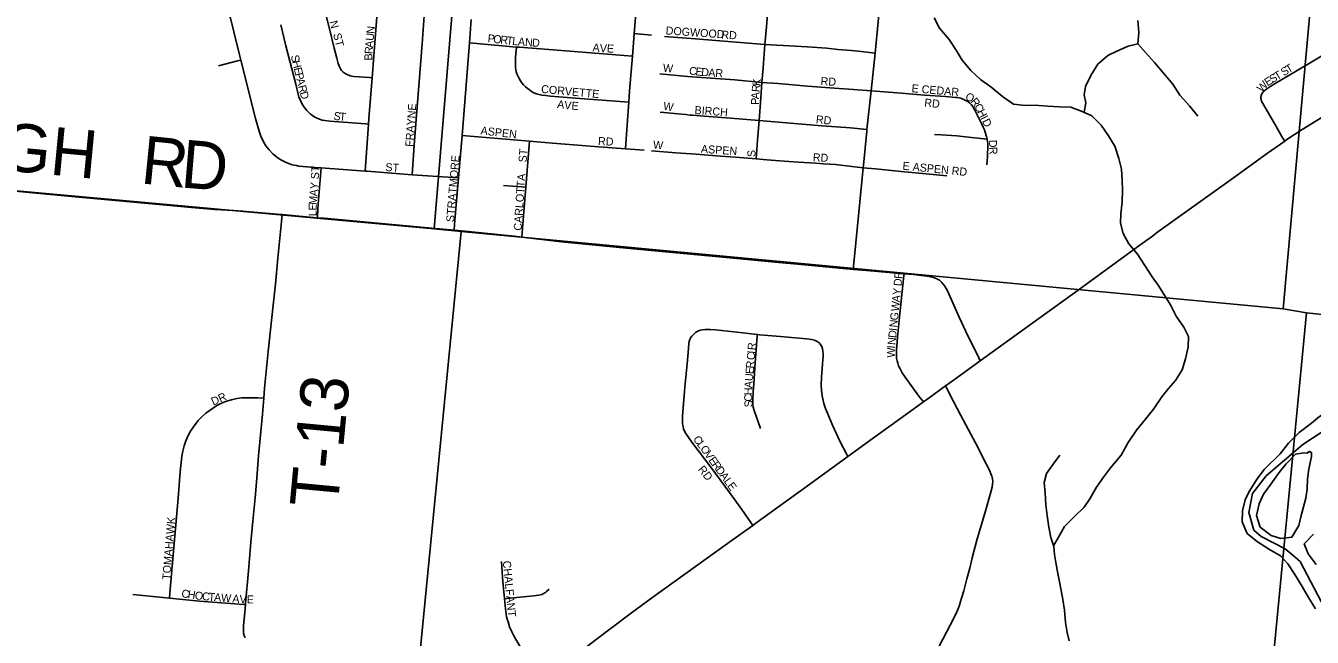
# Model space of a CAD drawing. Extents: x 0 to 680, y 0 to 440.
# Drawn here: x 150.24 to 174.06, y 261.68 to 273.01 of the extents above; entities that cross this region are included whole.
import ezdxf

# ---------------------------------------------------------------- set-up
doc = ezdxf.new("R2010")
doc.units = 0
for name, color, linetype in [('GM_X_County_Road', 7, 'Continuous'), ('GM_X_Major_River', 7, 'Continuous'), ('GM_X_Minor_River', 7, 'Continuous'), ('GM_X_Section', 7, 'Continuous'), ('GM_X_Township', 7, 'Continuous'), ('GM_X_Township_Road', 7, 'Continuous'), ('GM_X_Township_Road_Text', 7, 'Continuous'), ('GM_X_Township_Subdivision', 7, 'Continuous'), ('GM_X_Township_Subdivision_Text', 7, 'Continuous')]:
    doc.layers.add(name, color=color, linetype=linetype)

msp = doc.modelspace()

# ---------------------------------------------------------------- linework, layer by layer
at = {"layer": 'GM_X_County_Road'}
for points in [[(173.552, 270.873), (173.591, 270.9), (173.876, 271.086), (174.577, 271.522), (175.114, 271.853), (175.734, 272.237), (176.024, 272.413), (176.171, 272.503)], [(170.958, 269.009), (171.101, 269.114), (171.178, 269.173), (172.602, 270.194), (173.233, 270.648), (173.552, 270.873)], [(167.915, 266.802), (168.466, 267.203), (169.726, 268.114), (170.827, 268.913), (170.958, 269.009)], [(167.272, 266.337), (167.482, 266.489), (167.915, 266.802)], [(166.86, 266.04), (166.97, 266.119), (167.272, 266.337)], [(165.461, 265.029), (165.911, 265.355), (166.418, 265.724), (166.86, 266.04)], [(163.702, 263.755), (163.784, 263.815), (164.69, 264.471), (165.461, 265.029)], [(160.387, 261.323), (160.647, 261.525), (161.031, 261.816), (161.458, 262.137), (161.851, 262.423), (163.232, 263.417), (163.702, 263.755)]]:
    msp.add_lwpolyline(points, dxfattribs=at)
at = {"layer": 'GM_X_Major_River'}
for points in [[(176.639, 264.891), (176.325, 265.293), (176.105, 265.49), (175.902, 265.679), (175.709, 265.797), (175.55, 265.855), (175.337, 265.914), (175.178, 265.954), (174.983, 265.995), (174.774, 265.995), (174.565, 265.953), (174.349, 265.864), (174.198, 265.773), (174.046, 265.646), (173.821, 265.473), (173.625, 265.277), (173.471, 265.078)], [(173.471, 265.078), (173.172, 264.788), (173.03, 264.601), (172.894, 264.385), (172.819, 264.226), (172.772, 264.025), (172.767, 263.823), (172.856, 263.607), (173.048, 263.447), (173.27, 263.305), (173.475, 263.193), (173.608, 263.041), (173.74, 262.847), (173.877, 262.624), (173.99, 262.419), (174.122, 262.207)], [(173.75, 265.076), (173.579, 264.896), (173.45, 264.733), (173.295, 264.517), (173.16, 264.33), (173.078, 264.154), (173.031, 263.935), (173.097, 263.72), (173.301, 263.566), (173.478, 263.514), (173.686, 263.538), (173.811, 263.755), (173.851, 263.915), (173.903, 264.098), (173.943, 264.257), (173.965, 264.423), (173.976, 264.619), (173.998, 264.797), (174.047, 265.033)], [(174.047, 265.033), (174.049, 265.099), (174.025, 265.117), (174.008, 265.124), (173.965, 265.095), (173.906, 265.1), (173.75, 265.076)], [(174.086, 263.594), (173.915, 263.414), (173.987, 263.227), (174.137, 263.027)]]:
    msp.add_lwpolyline(points, dxfattribs=at)
at = {"layer": 'GM_X_Minor_River'}
for points in [[(170.524, 265.056), (170.651, 265.292), (170.809, 265.516), (170.971, 265.722), (171.122, 265.91), (171.279, 266.134), (171.4, 266.287), (171.532, 266.439), (171.653, 266.634), (171.715, 266.841), (171.766, 267.054), (171.768, 267.256), (171.687, 267.424), (171.541, 267.628), (171.437, 267.837), (171.344, 267.987), (171.21, 268.202), (171.099, 268.358), (170.959, 268.568), (170.825, 268.777), (170.668, 268.969), (170.563, 269.161), (170.512, 269.352), (170.52, 269.524), (170.541, 269.749), (170.549, 269.963), (170.54, 270.147), (170.531, 270.355), (170.48, 270.552), (170.405, 270.779), (170.289, 270.97), (170.155, 271.168), (169.979, 271.343), (169.802, 271.422), (169.589, 271.502), (169.381, 271.505), (169.168, 271.519), (168.996, 271.533), (168.687, 271.537), (168.527, 271.557), (168.327, 271.696), (168.11, 271.877), (167.922, 272.004), (167.74, 272.179), (167.576, 272.371), (167.465, 272.557), (167.337, 272.754), (167.162, 272.964), (167.063, 273.156)], [(169.837, 271.407), (169.869, 271.582), (169.841, 271.731), (169.861, 271.885), (169.959, 272.086), (170.092, 272.298), (170.278, 272.456), (170.445, 272.537), (170.654, 272.629), (170.833, 272.675), (170.853, 272.882), (170.832, 273.108)], [(170.833, 272.675), (170.973, 272.512), (171.143, 272.326), (171.307, 272.128), (171.482, 271.924), (171.61, 271.726), (171.786, 271.528), (171.944, 271.336)], [(169.559, 261.616), (169.526, 261.771), (169.493, 261.955), (169.472, 262.187), (169.44, 262.384), (169.412, 262.55), (169.379, 262.711), (169.352, 262.866), (169.313, 263.069), (169.291, 263.217), (169.276, 263.366), (169.219, 263.527), (169.186, 263.724), (169.153, 263.938), (169.126, 264.135), (169.118, 264.354), (169.097, 264.551), (169.141, 264.717), (169.262, 264.887), (169.385, 265.057)], [(169.272, 263.376), (169.361, 263.537), (169.471, 263.732), (169.651, 263.913), (169.838, 264.089), (169.941, 264.248), (170.069, 264.46), (170.196, 264.648), (170.323, 264.819), (170.524, 265.056)]]:
    msp.add_lwpolyline(points, dxfattribs=at)
at = {"layer": 'GM_X_Section'}
for points in [[(143.224, 286.379), (143.238, 286.516), (159.118, 285.103), (157.8, 269.245), (141.851, 270.701)], [(159.118, 285.103), (174.94, 283.442), (173.525, 267.764), (158.298, 269.195), (157.8, 269.245)], [(174.94, 283.442), (190.555, 281.787), (188.936, 266.093), (173.956, 267.691), (173.525, 267.764)], [(158.298, 269.195), (173.525, 267.764), (173.956, 267.691), (172.459, 252.156), (156.776, 253.584)], [(173.956, 267.691), (188.936, 266.093), (190.144, 265.991), (188.668, 250.631), (172.459, 252.156)]]:
    msp.add_lwpolyline(points, close=True, dxfattribs=at)
at = {"layer": 'GM_X_Township'}
for points in [[(174.424, 261.966), (173.841, 263.085), (173.708, 263.195), (173.561, 263.318), (173.118, 263.551), (172.978, 263.668), (172.885, 263.994), (172.954, 264.344), (173.211, 264.671), (173.887, 265.254), (174.564, 265.697)], [(174.564, 265.697), (173.887, 265.254), (173.211, 264.671), (172.954, 264.344), (172.885, 263.994), (172.978, 263.668), (173.118, 263.551), (173.561, 263.318), (173.708, 263.195), (173.841, 263.085), (174.424, 261.966)]]:
    msp.add_lwpolyline(points, dxfattribs=at)
at = {"layer": 'GM_X_Township_Road'}
for points in [[(165.965, 272.502), (166.035, 273.213)], [(165.891, 271.804), (165.965, 272.502)], [(165.815, 271.086), (165.891, 271.804)], [(165.746, 270.38), (165.751, 270.427), (165.812, 271.056), (165.815, 271.086)], [(143.887, 270.537), (144.178, 270.516), (144.988, 270.436), (146.804, 270.262), (147.532, 270.19), (148.112, 270.132), (148.841, 270.062), (149.664, 269.985), (150.298, 269.921), (151.221, 269.835), (151.9, 269.771), (152.774, 269.692), (153.309, 269.643), (153.74, 269.605), (154.084, 269.584)], [(165.564, 268.495), (165.569, 268.553), (165.587, 268.734), (165.746, 270.38)], [(154.084, 269.584), (154.256, 269.573)], [(154.256, 269.573), (154.32, 269.569), (154.894, 269.519), (154.987, 269.511)], [(154.645, 266.109), (154.661, 266.299), (154.727, 266.973), (154.786, 267.55), (154.822, 267.887), (154.859, 268.225), (154.908, 268.707), (154.974, 269.384), (154.987, 269.511)], [(154.987, 269.511), (155.233, 269.489), (155.635, 269.453)], [(155.635, 269.453), (155.764, 269.442), (156.827, 269.346), (157.551, 269.28), (158.17, 269.221)], [(158.17, 269.221), (158.372, 269.202), (159.096, 269.132), (159.289, 269.112), (159.426, 269.096)], [(159.426, 269.096), (160.157, 269.008), (161.362, 268.89), (163.343, 268.703), (164.118, 268.631), (164.598, 268.586), (165.179, 268.53), (165.564, 268.495)], [(165.564, 268.495), (165.806, 268.473), (166.502, 268.415)], [(166.502, 268.415), (166.679, 268.4), (166.873, 268.379), (166.969, 268.364), (167.018, 268.353), (167.066, 268.339), (167.112, 268.321), (167.156, 268.295), (167.195, 268.262), (167.228, 268.225), (167.257, 268.184), (167.306, 268.098), (167.526, 267.611), (167.649, 267.348), (167.839, 266.955), (167.86, 266.911), (167.915, 266.802)], [(167.085, 261.385), (167.359, 261.905), (167.467, 262.124), (167.524, 262.259), (167.55, 262.345), (167.564, 262.407), (167.607, 262.541), (167.667, 262.762), (167.72, 262.961), (167.761, 263.154), (167.851, 263.483), (168.015, 264.043), (168.097, 264.324), (168.134, 264.465), (168.143, 264.515), (168.145, 264.566), (168.14, 264.616), (168.128, 264.665), (168.112, 264.712), (168.093, 264.758), (168.072, 264.802), (167.98, 264.974), (167.872, 265.191), (167.552, 265.791), (167.419, 266.051), (167.289, 266.304), (167.272, 266.337)], [(154.304, 262.285), (154.305, 262.292), (154.307, 262.309), (154.361, 262.914), (154.373, 263.059), (154.407, 263.445), (154.442, 263.832), (154.486, 264.266), (154.51, 264.556), (154.55, 265.041), (154.619, 265.815), (154.645, 266.109)], [(154.307, 261.673), (154.297, 261.687), (154.283, 261.714), (154.272, 261.758), (154.268, 261.804), (154.27, 261.898), (154.293, 262.14), (154.304, 262.285)]]:
    msp.add_lwpolyline(points, dxfattribs=at)
at = {"layer": 'GM_X_Township_Subdivision'}
for points in [[(154.221, 272.373), (154.198, 272.468), (153.999, 273.271), (153.93, 273.554), (153.795, 274.071), (153.761, 274.207)], [(156.65, 272.046), (156.68, 272.45), (156.737, 273.174), (156.763, 273.534), (156.798, 274.019), (156.804, 274.097)], [(155.701, 273.591), (155.857, 272.975), (155.95, 272.595), (156, 272.406), (156.025, 272.311), (156.038, 272.266), (156.047, 272.246), (156.057, 272.226), (156.072, 272.201), (156.087, 272.18), (156.103, 272.162), (156.118, 272.148), (156.136, 272.134), (156.155, 272.122), (156.176, 272.11), (156.198, 272.099), (156.22, 272.091), (156.247, 272.082), (156.277, 272.076), (156.311, 272.07), (156.409, 272.061), (156.599, 272.049), (156.65, 272.046)], [(161.504, 272.864), (161.54, 273.302)], [(163.926, 272.664), (163.954, 272.99), (163.988, 273.381)], [(157.391, 270.25), (157.43, 270.796), (157.485, 271.506), (157.517, 271.895), (157.576, 272.671), (157.616, 273.191)], [(158.452, 272.691), (158.486, 273.127)], [(156.585, 271.186), (156.536, 271.19), (156.112, 271.221), (155.869, 271.239), (155.773, 271.252), (155.725, 271.263), (155.679, 271.277), (155.633, 271.295), (155.59, 271.317), (155.549, 271.344), (155.511, 271.374), (155.441, 271.442), (155.409, 271.479), (155.381, 271.518), (155.355, 271.559), (155.312, 271.647), (155.295, 271.692), (155.281, 271.739), (155.236, 271.928), (155.052, 272.634), (154.958, 273.025)], [(161.471, 272.446), (161.497, 272.771), (161.504, 272.864)], [(161.504, 272.864), (161.828, 272.835)], [(162.063, 272.812), (162.642, 272.767), (163.926, 272.664)], [(158.316, 270.979), (158.452, 272.691)], [(158.452, 272.691), (159.323, 272.614)], [(159.323, 272.614), (159.309, 272.42), (159.305, 272.35), (159.305, 272.271), (159.308, 272.232), (159.313, 272.196), (159.321, 272.156), (159.334, 272.116), (159.367, 272.042), (159.398, 271.99), (159.427, 271.949), (159.456, 271.915), (159.491, 271.879), (159.523, 271.851), (159.565, 271.82), (159.605, 271.794), (159.649, 271.769), (159.698, 271.748), (159.744, 271.733), (159.797, 271.722), (159.865, 271.714), (159.954, 271.704), (160.42, 271.67), (161.405, 271.593)], [(159.323, 272.614), (159.38, 272.61), (160.855, 272.496), (161.471, 272.446)], [(163.867, 271.956), (163.891, 272.228), (163.926, 272.664)], [(163.926, 272.664), (164.484, 272.628), (164.709, 272.616), (165.07, 272.592), (165.276, 272.572), (165.528, 272.551), (165.71, 272.532), (165.965, 272.502)], [(173.552, 270.873), (173.507, 270.948), (173.385, 271.154), (173.164, 271.536), (173.146, 271.569), (173.13, 271.6), (173.124, 271.617), (173.118, 271.632), (173.115, 271.641), (173.113, 271.653), (173.112, 271.665), (173.111, 271.678), (173.112, 271.691), (173.114, 271.702), (173.116, 271.714), (173.119, 271.723), (173.126, 271.74), (173.131, 271.75), (173.14, 271.764), (173.146, 271.773), (173.154, 271.782), (173.167, 271.796), (173.176, 271.804), (173.19, 271.816), (173.22, 271.838), (173.258, 271.865), (173.295, 271.89), (173.375, 271.94), (174.021, 272.321), (174.659, 272.704)], [(153.806, 272.267), (154.158, 272.357), (154.221, 272.373)], [(155.705, 270.377), (155.588, 270.386), (155.296, 270.41), (155.248, 270.418), (155.199, 270.428), (155.151, 270.441), (155.059, 270.476), (154.971, 270.52), (154.928, 270.546), (154.888, 270.574), (154.812, 270.637), (154.743, 270.708), (154.682, 270.786), (154.631, 270.871), (154.589, 270.961), (154.557, 271.054), (154.494, 271.289), (154.221, 272.373)], [(161.405, 271.593), (161.419, 271.803), (161.471, 272.446)], [(161.978, 272.116), (162.495, 272.068), (162.753, 272.049), (163.368, 272.004), (163.867, 271.956)], [(156.585, 271.186), (156.593, 271.293), (156.65, 272.046)], [(163.82, 271.252), (163.848, 271.671), (163.867, 271.956)], [(163.867, 271.956), (164.169, 271.938), (164.714, 271.89), (165.13, 271.856), (165.565, 271.826), (165.891, 271.804)], [(165.891, 271.804), (166.216, 271.779), (166.455, 271.76), (166.88, 271.726), (167.273, 271.697), (167.459, 271.682), (167.493, 271.678), (167.521, 271.673), (167.552, 271.665), (167.577, 271.657), (167.598, 271.649), (167.642, 271.627)], [(168.042, 270.908), (168.03, 270.96), (168.004, 271.038), (167.99, 271.078), (167.969, 271.133), (167.935, 271.199), (167.812, 271.443), (167.78, 271.499), (167.749, 271.543), (167.713, 271.583), (167.69, 271.601), (167.663, 271.617), (167.642, 271.627)], [(161.342, 270.73), (161.375, 271.173), (161.405, 271.593)], [(161.987, 271.407), (162.321, 271.38), (162.46, 271.365), (162.544, 271.355), (162.586, 271.351), (162.807, 271.333), (163.287, 271.298), (163.82, 271.252)], [(156.522, 270.315), (156.585, 271.186)], [(163.763, 270.542), (163.789, 270.892), (163.82, 271.252)], [(163.82, 271.252), (163.962, 271.239), (164.977, 271.156), (165.509, 271.115), (165.815, 271.086)], [(158.25, 270.189), (158.316, 270.979)], [(158.316, 270.979), (159.566, 270.871)], [(167.064, 270.996), (167.19, 270.987), (167.384, 270.974), (167.477, 270.967), (167.698, 270.943), (168.042, 270.908)], [(168.034, 270.432), (168.045, 270.578), (168.05, 270.673), (168.053, 270.713), (168.053, 270.77), (168.052, 270.825), (168.048, 270.866), (168.042, 270.908)], [(159.5, 270.018), (159.566, 270.871)], [(159.566, 270.871), (159.991, 270.834), (160.769, 270.772), (161.342, 270.73)], [(161.342, 270.73), (161.687, 270.707)], [(161.827, 270.694), (162.273, 270.657), (162.655, 270.63), (163.101, 270.594), (163.384, 270.572), (163.763, 270.542)], [(163.763, 270.542), (163.961, 270.525), (164.281, 270.499), (164.548, 270.482), (164.867, 270.462), (165.012, 270.452), (165.13, 270.445), (165.23, 270.438), (165.534, 270.404), (165.746, 270.38)], [(155.635, 269.453), (155.637, 269.483), (155.654, 269.709), (155.705, 270.377)], [(156.522, 270.315), (155.705, 270.377)], [(157.391, 270.25), (157.236, 270.261), (156.558, 270.313), (156.522, 270.315)], [(158.25, 270.189), (158.155, 270.195), (157.391, 270.25)], [(165.746, 270.38), (165.974, 270.358), (166.513, 270.305), (166.913, 270.265), (167.295, 270.227)], [(158.17, 269.221), (158.179, 269.331), (158.25, 270.189)], [(159.084, 270.047), (159.5, 270.018)], [(159.426, 269.096), (159.433, 269.18), (159.5, 270.018)], [(166.86, 266.04), (166.779, 266.15), (166.522, 266.498), (166.468, 266.579), (166.422, 266.666), (166.402, 266.71), (166.386, 266.757), (166.373, 266.805), (166.365, 266.853), (166.361, 266.902), (166.363, 267), (166.383, 267.24), (166.426, 267.671), (166.499, 268.382), (166.502, 268.415)], [(163.702, 263.755), (163.664, 263.81), (163.496, 264.048), (163.27, 264.363), (162.923, 264.831), (162.691, 265.142), (162.573, 265.295), (162.514, 265.374), (162.46, 265.455), (162.436, 265.5), (162.42, 265.544), (162.41, 265.589), (162.4, 265.634), (162.397, 265.682), (162.399, 265.779), (162.445, 266.312), (162.485, 266.746), (162.509, 267.031), (162.518, 267.132), (162.522, 267.158), (162.528, 267.179), (162.548, 267.226), (162.572, 267.26), (162.602, 267.292), (162.641, 267.325), (162.686, 267.351), (162.726, 267.368), (162.771, 267.377), (162.819, 267.383), (162.868, 267.383), (162.914, 267.382), (163.009, 267.374), (163.352, 267.337), (163.788, 267.291)], [(163.847, 265.549), (163.729, 265.883), (163.711, 265.943), (163.703, 265.991), (163.7, 266.046), (163.702, 266.088), (163.709, 266.235), (163.719, 266.378), (163.747, 266.764), (163.785, 267.258), (163.788, 267.291)], [(163.788, 267.291), (163.826, 267.287), (164.212, 267.25), (164.694, 267.21), (164.791, 267.198), (164.841, 267.184), (164.884, 267.164), (164.922, 267.139), (164.953, 267.104), (164.977, 267.067), (164.99, 267.025), (165.001, 266.981), (165.006, 266.935), (165.006, 266.887), (164.994, 266.743), (164.974, 266.501), (164.97, 266.354), (164.972, 266.256), (164.983, 266.157), (165.018, 266.015), (165.048, 265.922), (165.083, 265.831), (165.179, 265.608), (165.321, 265.299), (165.435, 265.078), (165.461, 265.029)], [(152.898, 262.406), (152.906, 262.501), (153.057, 264.26), (153.097, 264.744), (153.128, 265.035), (153.146, 265.131), (153.171, 265.226), (153.203, 265.319), (153.241, 265.409), (153.287, 265.497), (153.341, 265.579), (153.432, 265.695), (153.499, 265.766), (153.573, 265.831), (153.651, 265.891), (153.774, 265.972), (153.86, 266.018), (153.952, 266.054), (154.047, 266.082), (154.143, 266.102), (154.24, 266.114), (154.338, 266.119), (154.485, 266.117), (154.534, 266.115), (154.645, 266.109)], [(159.102, 262.394), (159.101, 262.403), (159.076, 262.646), (159.066, 262.792), (159.046, 263.087)], [(159.102, 262.394), (159.146, 262.399), (159.641, 262.449), (159.741, 262.465), (159.792, 262.476), (159.818, 262.487), (159.839, 262.497), (159.852, 262.504), (159.865, 262.512), (159.883, 262.528), (159.929, 262.576)], [(152.219, 262.475), (152.346, 262.462), (152.898, 262.406)], [(152.898, 262.406), (153.453, 262.35), (154.188, 262.294), (154.283, 262.286), (154.304, 262.285)], [(159.855, 260.909), (159.795, 260.984), (159.643, 261.173), (159.495, 261.369), (159.383, 261.53), (159.306, 261.655), (159.267, 261.724), (159.237, 261.785), (159.198, 261.874), (159.168, 261.968), (159.152, 262.019), (159.142, 262.062), (159.132, 262.11), (159.12, 262.207), (159.102, 262.394)]]:
    msp.add_lwpolyline(points, dxfattribs=at)

# ---------------------------------------------------------------- texts
at = {"layer": 'GM_X_Township_Road_Text'}
for s, height, rotation, p in [('GERLAUGH', 0.8894, 354.5349, (144.875, 270.808)), ('R', 0.889, 354.2451, (152.348, 270.091)), ('D', 0.889, 355.2013, (153.09, 270.016)), ('T-13', 0.8894, 84.6178, (156.01, 264.054))]:
    msp.add_text(s, height=height, rotation=rotation, dxfattribs=at).set_placement(p)
at = {"layer": 'GM_X_Township_Subdivision_Text'}
for s, height, rotation, p in [('N', 0.148, 284.3013, (155.862, 273.085)), ('ST', 0.1482, 284.0363, (155.927, 272.854)), ('U', 0.148, 84.6809, (156.679, 272.725)), ('N', 0.148, 84.6934, (156.691, 272.855)), ('P', 0.148, 353.8137, (158.785, 272.705)), ('O', 0.148, 353.8135, (158.889, 272.694)), ('R', 0.148, 353.8177, (159.019, 272.68)), ('T', 0.148, 353.8001, (159.135, 272.667)), ('DOGWOOD', 0.1482, 356.0809, (162.084, 272.849)), ('RD', 0.1482, 356.989, (163.115, 272.771)), ('R', 0.148, 85.2958, (156.658, 272.479)), ('A', 0.148, 84.6918, (156.667, 272.595)), ('L', 0.148, 353.9055, (159.24, 272.656)), ('A', 0.148, 355.2745, (159.347, 272.645)), ('N', 0.148, 356.0294, (159.479, 272.634)), ('D', 0.148, 356.0519, (159.609, 272.625)), ('A', 0.148, 354.7472, (160.729, 272.536)), ('V', 0.148, 356.5757, (160.864, 272.523)), ('E', 0.148, 356.9863, (160.995, 272.516)), ('S', 0.148, 283.5823, (155.144, 272.449)), ('H', 0.148, 283.5837, (155.169, 272.347)), ('B', 0.148, 88.3485, (156.654, 272.363)), ('E', 0.148, 283.5823, (155.199, 272.22)), ('P', 0.148, 283.5823, (155.224, 272.119)), ('W', 0.148, 355.6039, (162.033, 272.157)), ('C', 0.148, 353.7094, (162.516, 272.105)), ('E', 0.148, 354.0135, (162.634, 272.092)), ('D', 0.148, 355.5448, (162.742, 272.081)), ('A', 0.148, 356.0348, (162.873, 272.071)), ('R', 0.148, 356.0518, (163.003, 272.062)), ('S', 0.148, 31.5869, (173.322, 271.94)), ('T', 0.148, 31.3784, (173.411, 271.995)), ('S', 0.148, 31.3784, (173.534, 272.07)), ('T', 0.148, 31.3667, (173.623, 272.124)), ('A', 0.148, 283.5803, (155.248, 272.018)), ('R', 0.148, 283.5872, (155.279, 271.891)), ('CORVETTE', 0.1482, 354.8053, (159.777, 271.766)), ('R', 0.148, 83.9052, (163.826, 271.773)), ('K', 0.148, 83.836, (163.839, 271.89)), ('RD', 0.1482, 356.9887, (164.954, 271.91)), ('E CEDAR', 0.1482, 355.1554, (166.637, 271.779)), ('W', 0.148, 46.5041, (173.126, 271.767)), ('E', 0.148, 32.6179, (173.235, 271.884)), ('D', 0.148, 286.3408, (155.309, 271.769)), ('A', 0.148, 353.1759, (160.073, 271.487)), ('P', 0.148, 89.3033, (163.816, 271.542)), ('A', 0.148, 85.7119, (163.817, 271.644)), ('RD', 0.1482, 353.9883, (166.872, 271.515)), ('O', 0.148, 331.7585, (167.621, 271.654)), ('R', 0.148, 308.5991, (167.724, 271.602)), ('S', 0.148, 352.2582, (155.93, 271.27)), ('T', 0.148, 354.421, (156.039, 271.256)), ('FRAYNE', 0.1482, 85.9147, (157.412, 270.762)), ('V', 0.148, 353.5312, (160.203, 271.471)), ('E', 0.148, 355.7277, (160.339, 271.456)), ('W', 0.148, 351.2507, (162.035, 271.453)), ('BIRCH', 0.1482, 355.914, (162.619, 271.375)), ('C', 0.148, 300.2057, (167.794, 271.515)), ('H', 0.148, 297.7723, (167.852, 271.415)), ('RD', 0.1482, 353.994, (164.864, 271.205)), ('I', 0.148, 297.3372, (167.913, 271.3)), ('D', 0.148, 296.179, (167.942, 271.242)), ('ASPEN', 0.1482, 353.5154, (158.655, 270.997)), ('RD', 0.1482, 356.9887, (160.832, 270.801)), ('ST', 0.1482, 86.4254, (159.511, 270.475)), ('W', 0.148, 355.6039, (161.85, 270.736)), ('ASPEN', 0.1482, 356.0991, (162.737, 270.657)), ('S', 0.148, 90, (163.75, 270.577)), ('D', 0.148, 273.2914, (168.072, 270.892)), ('R', 0.148, 272.6969, (168.079, 270.762)), ('ST', 0.1482, 356.4186, (156.893, 270.318)), ('STRATMORE', 0.1482, 85.2364, (158.168, 269.367)), ('RD', 0.1482, 356.9833, (164.81, 270.501)), ('E ASPEN RD', 0.1482, 354.3592, (166.469, 270.344)), ('ST', 0.1482, 86.4254, (155.663, 270.162)), ('CARLOTTA', 0.1482, 86.1853, (159.42, 269.21)), ('A', 0.148, 84.6374, (155.637, 269.843)), ('Y', 0.148, 84.6484, (155.649, 269.973)), ('M', 0.148, 85.7612, (155.625, 269.688)), ('E', 0.148, 89.2623, (155.624, 269.586)), ('L', 0.148, 89.8907, (155.624, 269.482)), ('D', 0.148, 84.1426, (166.454, 268.18)), ('R', 0.148, 86.141, (166.468, 268.316)), ('Y', 0.148, 84.1407, (166.437, 268.012)), ('W', 0.148, 84.1472, (166.406, 267.713)), ('A', 0.148, 84.1426, (166.423, 267.882)), ('G', 0.148, 84.1407, (166.389, 267.545)), ('D', 0.148, 84.1437, (166.355, 267.22)), ('I', 0.148, 84.1491, (166.369, 267.35)), ('N', 0.148, 84.1437, (166.375, 267.415)), ('R', 0.148, 85.0973, (163.75, 266.994)), ('N', 0.148, 84.2089, (166.342, 267.09)), ('C', 0.148, 85.1123, (163.735, 266.812)), ('I', 0.148, 85.0984, (163.745, 266.929)), ('W', 0.148, 88.7053, (166.333, 266.859)), ('I', 0.148, 85.1855, (166.337, 267.026)), ('E', 0.148, 85.1011, (163.712, 266.552)), ('R', 0.148, 85.0973, (163.721, 266.656)), ('A', 0.148, 85.2953, (163.691, 266.292)), ('U', 0.148, 85.0984, (163.701, 266.422)), ('DR', 0.1482, 23.9614, (153.709, 265.972)), ('C', 0.148, 92.4901, (163.694, 266.05)), ('H', 0.148, 89.0929, (163.689, 266.165)), ('S', 0.148, 92.4872, (163.698, 265.945)), ('C', 0.148, 306.1559, (162.588, 265.35)), ('L', 0.148, 306.158, (162.657, 265.255)), ('O', 0.148, 306.1551, (162.719, 265.171)), ('V', 0.148, 306.1611, (162.796, 265.066)), ('E', 0.148, 306.165, (162.873, 264.96)), ('R', 0.148, 306.1559, (162.934, 264.876)), ('RD', 0.1482, 308.6634, (162.677, 264.789)), ('D', 0.148, 306.1532, (163.003, 264.781)), ('A', 0.148, 306.1611, (163.08, 264.676)), ('L', 0.148, 306.165, (163.157, 264.571)), ('E', 0.148, 306.2396, (163.219, 264.486)), ('TOMAHAWK', 0.1482, 85.2364, (152.911, 262.74)), ('CHALFANT', 0.1482, 275.478, (159.071, 263.093)), ('C', 0.148, 351.3083, (153.112, 262.426)), ('H', 0.148, 351.3132, (153.228, 262.409)), ('O', 0.148, 352.723, (153.361, 262.388)), ('C', 0.148, 355.3241, (153.498, 262.371)), ('T', 0.148, 355.563, (153.616, 262.361)), ('A', 0.148, 355.5585, (153.72, 262.353)), ('W', 0.148, 355.5568, (153.85, 262.343)), ('A', 0.148, 355.5561, (154.058, 262.327)), ('V', 0.148, 357.0261, (154.192, 262.317)), ('E', 0.148, 359.7509, (154.33, 262.31))]:
    msp.add_text(s, height=height, rotation=rotation, dxfattribs=at).set_placement(p)

doc.saveas('drawing.dxf')
